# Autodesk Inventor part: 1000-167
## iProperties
Created: 2007-03
Part Number: 1000-167
Document SubType Name: Modeling
Designer: Andy Moles
Material: Steel
Mass: 62.642 g
Surface Area: 53.6336 cm^2
Volume: 7.97987 cm^3
Density: 7.85 g/cm^3
Author: Andy Moles
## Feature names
1. Base1
